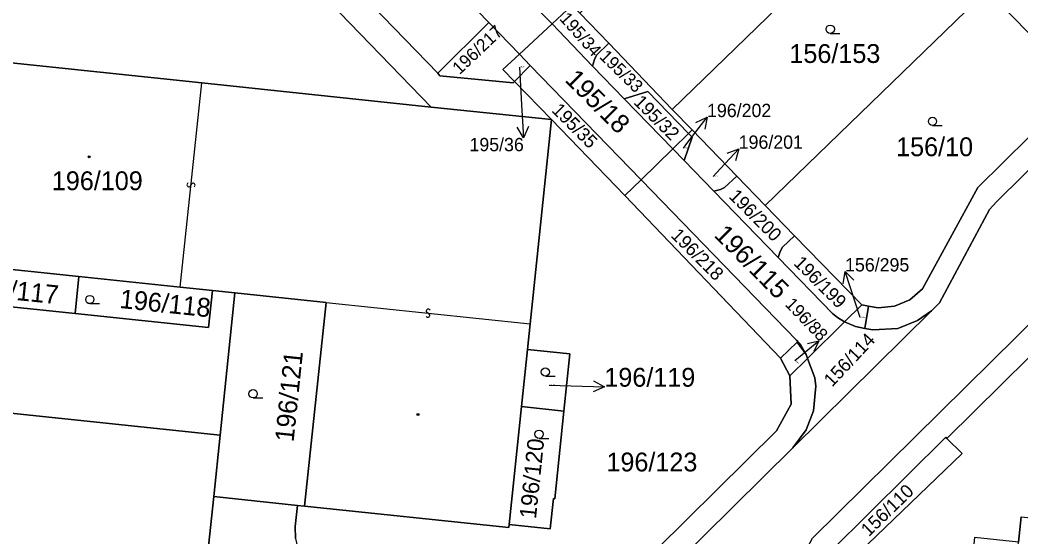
# Model space of a CAD drawing. Extents: x -598233 to -596890, y -1157848 to -1156431.
# Drawn here: x -597801.7 to -597711.3, y -1156746.8 to -1156700.1 of the extents above; entities that cross this region are included whole.
import ezdxf

# ---------------------------------------------------------------- set-up
doc = ezdxf.new("R2010")
doc.units = 0
for name, color, linetype in [('Level 1', 7, 'Continuous'), ('Level 13', 7, 'Continuous'), ('Level 3', 7, 'Continuous'), ('Level 4', 7, 'Continuous'), ('Level 5', 7, 'Continuous'), ('Level 57', 7, 'Continuous'), ('Level 60', 7, 'Continuous')]:
    doc.layers.add(name, color=color, linetype=linetype)

msp = doc.modelspace()

# ---------------------------------------------------------------- linework, layer by layer
at = {"layer": 'Level 1'}
for points in [[(-597786.04, -1156675.75), (-597787.57, -1156684.23), (-597764.57, -1156707.96)], [(-597759.36, -1156700.34), (-597781.05, -1156677.98)], [(-597785.73, -1156682.48), (-597763.99, -1156704.91)], [(-597742.79, -1156708.17), (-597722.73, -1156688.74)], [(-597686.53, -1156689.82), (-597686.5, -1156690.8), (-597687.19, -1156693.55), (-597687.81, -1156694.8), (-597689.13, -1156696.52), (-597689.98, -1156697.26), (-597690.52, -1156697.64), (-597698.5, -1156701.76), (-597699.2, -1156702.39), (-597713.49, -1156716.51), (-597714.13, -1156717.22), (-597718.64, -1156725.65), (-597719.37, -1156726.36)], [(-597750.17, -1156770.82), (-597735.18, -1156755.99), (-597734.6, -1156755.26), (-597730.11, -1156746.9), (-597683.93, -1156701.31), (-597681.14, -1156698.43), (-597679.19, -1156696.78), (-597678.75, -1156696.58)], [(-597714.33, -1156697.41), (-597734.39, -1156716.85)], [(-597714.33, -1156697.41), (-597705.92, -1156706.09)], [(-597755.85, -1156698.19), (-597753.66, -1156700.46)], [(-597753.66, -1156700.46), (-597751.84, -1156698.77)], [(-597751.16, -1156699.47), (-597748.53, -1156702.2)], [(-597763.99, -1156704.91), (-597759.36, -1156700.34)], [(-597759.36, -1156700.34), (-597756.61, -1156703.19)], [(-597756.61, -1156703.19), (-597753.66, -1156700.46)], [(-597753.66, -1156700.46), (-597749.99, -1156704.26)], [(-597749.99, -1156704.26), (-597749.83, -1156703.68), (-597749.63, -1156703.29), (-597748.53, -1156702.2)], [(-597748.53, -1156702.2), (-597742.79, -1156708.17)], [(-597757.04, -1156705.66), (-597758.1, -1156704.57), (-597756.61, -1156703.19)], [(-597756.61, -1156703.19), (-597755.62, -1156704.21)], [(-597803.73, -1156704.01), (-597803.71, -1156703.85), (-597785.3, -1156705.78)], [(-597763.99, -1156704.91), (-597763.8, -1156705.15), (-597757.17, -1156705.79), (-597757.04, -1156705.66)], [(-597755.62, -1156704.21), (-597757.04, -1156705.66)], [(-597755.62, -1156704.21), (-597745.61, -1156714.53)], [(-597747.13, -1156707.21), (-597749.99, -1156704.26)], [(-597785.3, -1156705.78), (-597764.57, -1156707.96)], [(-597753.71, -1156709.1), (-597757.04, -1156705.66)], [(-597747.13, -1156707.21), (-597745, -1156706.57), (-597741.34, -1156710.34)], [(-597725.07, -1156725.94), (-597724.19, -1156726.11), (-597722.7, -1156725.95), (-597721.32, -1156725.36), (-597720.17, -1156724.39), (-597715.17, -1156715.23), (-597705.92, -1156706.09)], [(-597742.75, -1156711.73), (-597747.13, -1156707.21)], [(-597764.57, -1156707.96), (-597753.71, -1156709.1)], [(-597741.01, -1156710.02), (-597742.79, -1156708.17)], [(-597753.71, -1156709.1), (-597755.63, -1156727.55)], [(-597753.71, -1156709.1), (-597747.07, -1156715.96)], [(-597742.75, -1156711.73), (-597741.34, -1156710.34)], [(-597741.73, -1156712.78), (-597741, -1156710.69), (-597741.34, -1156710.34)], [(-597741.34, -1156710.34), (-597741.01, -1156710.02)], [(-597741.01, -1156710.02), (-597736.95, -1156714.21)], [(-597808.32, -1156710.99), (-597809.81, -1156725.24), (-597796.75, -1156726.6)], [(-597796.4, -1156723.28), (-597805.64, -1156722.31), (-597804.5, -1156711.39)], [(-597745.61, -1156714.53), (-597742.75, -1156711.73)], [(-597741.73, -1156712.78), (-597742.75, -1156711.73)], [(-597739.05, -1156715.55), (-597741.73, -1156712.78)], [(-597745.61, -1156714.53), (-597747.07, -1156715.96)], [(-597745.61, -1156714.53), (-597731.56, -1156729.03), (-597731.19, -1156729.48), (-597730.7, -1156730.32)], [(-597739.05, -1156715.55), (-597738.44, -1156715.42), (-597738.06, -1156715.24), (-597736.95, -1156714.21)], [(-597736.95, -1156714.21), (-597734.39, -1156716.85)], [(-597733.22, -1156721.56), (-597739.05, -1156715.55)], [(-597733.02, -1156730.64), (-597747.07, -1156715.96)], [(-597734.39, -1156716.85), (-597731.74, -1156719.58)], [(-597733.22, -1156721.56), (-597733.04, -1156721.02), (-597732.82, -1156720.63), (-597731.74, -1156719.58)], [(-597731.74, -1156719.58), (-597725.66, -1156725.82)], [(-597727.22, -1156727.36), (-597727.87, -1156726.98), (-597728.31, -1156726.62), (-597733.22, -1156721.56)], [(-597796.4, -1156723.28), (-597796.75, -1156726.6)], [(-597796.4, -1156723.28), (-597787.25, -1156724.23)], [(-597796.75, -1156726.6), (-597784.7, -1156727.86), (-597784.35, -1156724.54)], [(-597787.25, -1156724.23), (-597784.35, -1156724.54)], [(-597784.35, -1156724.54), (-597782.31, -1156724.75)], [(-597782.31, -1156724.75), (-597783.65, -1156737.59)], [(-597782.31, -1156724.75), (-597774.08, -1156725.61)], [(-597776.01, -1156744.01), (-597774.08, -1156725.61)], [(-597727.22, -1156727.36), (-597725.66, -1156725.82)], [(-597725.66, -1156725.82), (-597725.07, -1156725.94)], [(-597717.97, -1156737.89), (-597705.61, -1156725.68)], [(-597731.89, -1156738.74), (-597719.37, -1156726.36)], [(-597725.07, -1156725.94), (-597725.4, -1156727.96)], [(-597719.37, -1156726.36), (-597720.64, -1156727.23), (-597722.41, -1156727.95), (-597724.67, -1156728.09), (-597725.4, -1156727.96)], [(-597755.87, -1156729.85), (-597755.63, -1156727.55)], [(-597730.57, -1156730.67), (-597727.22, -1156727.36)], [(-597725.4, -1156727.96), (-597726.23, -1156727.78), (-597727.22, -1156727.36)], [(-597730.7, -1156730.32), (-597731.52, -1156729.19), (-597733.02, -1156730.64)], [(-597756.41, -1156735.02), (-597755.87, -1156729.85)], [(-597752.58, -1156735.42), (-597752.04, -1156730.25), (-597755.87, -1156729.85)], [(-597730.7, -1156730.32), (-597730.57, -1156730.67)], [(-597733.02, -1156730.64), (-597732.17, -1156732.25)], [(-597732.17, -1156732.25), (-597730.57, -1156730.67)], [(-597731.89, -1156738.74), (-597730.68, -1156737.11), (-597730.03, -1156735.4), (-597729.82, -1156733.16), (-597729.92, -1156732.43), (-597730.57, -1156730.67)], [(-597760.41, -1156763.93), (-597733.37, -1156737.22), (-597732.06, -1156734.8), (-597732.17, -1156732.25)], [(-597813.46, -1156734.47), (-597783.65, -1156737.59)], [(-597757.52, -1156745.67), (-597756.41, -1156735.02)], [(-597752.58, -1156735.42), (-597753.41, -1156743.34), (-597753.54, -1156743.32), (-597753.82, -1156746.05), (-597757.52, -1156745.67)], [(-597752.58, -1156735.42), (-597756.41, -1156735.02)], [(-597783.65, -1156737.59), (-597784.23, -1156743.15)], [(-597717.97, -1156737.89), (-597718.07, -1156737.79), (-597728.48, -1156748.08), (-597731.29, -1156753.36)], [(-597731.29, -1156753.36), (-597716.61, -1156739.26), (-597717.97, -1156737.89)], [(-597731.89, -1156738.74), (-597756.11, -1156762.68)], [(-597784.23, -1156743.15), (-597784.97, -1156750.15)], [(-597784.23, -1156743.15), (-597776.66, -1156743.94)], [(-597776.66, -1156743.94), (-597776.86, -1156745.86), (-597776.85, -1156746.93), (-597776.61, -1156747.97), (-597776.15, -1156748.94), (-597775.48, -1156749.77), (-597762.97, -1156762.45), (-597761.74, -1156763.35), (-597760.41, -1156763.93)], [(-597776.01, -1156744.01), (-597776.66, -1156743.94)], [(-597757.52, -1156745.67), (-597757.55, -1156745.95), (-597776.01, -1156744.01)], [(-597711.51, -1156747.26), (-597711.27, -1156744.96), (-597692.75, -1156746.9)]]:
    msp.add_lwpolyline(points, dxfattribs=at)
at = {"layer": 'Level 13'}
for centre, start, end in [((-597786.463, -1156714.979), 121.33948, 353.43748), ((-597786.097, -1156715.02), 301.12502, 173.71503), ((-597764.88, -1156726.763), 211.15574, 83.74574), ((-597764.839, -1156726.397), 31.37019, 263.46819)]:
    msp.add_arc(centre, 0.184, start, end, dxfattribs=at)
at = {"layer": 'Level 3'}
for points in [[(-597787.25, -1156724.23), (-597785.3, -1156705.78)], [(-597774.08, -1156725.61), (-597755.63, -1156727.55)]]:
    msp.add_lwpolyline(points, dxfattribs=at)
at = {"layer": 'Level 5'}
for p, q in [((-597728.52, -1156701.31), (-597727.645, -1156701.31)), ((-597719.28, -1156709.63), (-597718.405, -1156709.63)), ((-597795.42, -1156725.72), (-597794.545, -1156725.72)), ((-597754.26, -1156732.27), (-597753.385, -1156732.27)), ((-597780.67, -1156734.23), (-597779.795, -1156734.23)), ((-597754.83, -1156737.89), (-597753.955, -1156737.89))]:
    msp.add_line(p, q, dxfattribs=at)
for centre, radius in [((-597728.52, -1156700.935), 0.375), ((-597719.28, -1156709.255), 0.375), ((-597795.47, -1156712.46), 0.09), ((-597795.47, -1156712.46), 0.0521), ((-597795.42, -1156725.345), 0.375), ((-597754.26, -1156731.895), 0.375), ((-597780.67, -1156733.855), 0.375), ((-597765.77, -1156735.73), 0.09), ((-597765.77, -1156735.73), 0.0521), ((-597754.83, -1156737.515), 0.375)]:
    msp.add_circle(centre, radius, dxfattribs=at)
at = {"layer": 'Level 57'}
for p, q in [((-597756.59, -1156704.37), (-597756.406, -1156707.754)), ((-597756.406, -1156707.754), (-597756.243, -1156710.75)), ((-597741.468, -1156711.257), (-597739.65, -1156708.87)), ((-597741.79, -1156711.68), (-597741.468, -1156711.257)), ((-597738.812, -1156713.946), (-597736.79, -1156711.73)), ((-597739.09, -1156714.25), (-597738.812, -1156713.946)), ((-597726.249, -1156725.663), (-597727.178, -1156722.81)), ((-597725.82, -1156726.98), (-597726.249, -1156725.663)), ((-597731.73, -1156730.85), (-597729.562, -1156729.08)), ((-597753.91, -1156733.07), (-597751.929, -1156733.13)), ((-597751.929, -1156733.13), (-597748.93, -1156733.22))]:
    msp.add_line(p, q, dxfattribs=at)
for points in [[(-597740.654, -1156709.363), (-597739.65, -1156708.87), (-597739.858, -1156709.969)], [(-597755.798, -1156709.724), (-597756.243, -1156710.75), (-597756.797, -1156709.778)], [(-597737.833, -1156712.132), (-597736.79, -1156711.73), (-597737.094, -1156712.806)], [(-597727.344, -1156723.916), (-597727.178, -1156722.81), (-597726.393, -1156723.606)], [(-597730.58, -1156729.309), (-597729.562, -1156729.08), (-597729.99, -1156730.032)], [(-597749.915, -1156732.69), (-597748.93, -1156733.22), (-597749.945, -1156733.69)]]:
    msp.add_lwpolyline(points, dxfattribs=at)
at = {"layer": 'Level 60'}
for points in [[(-597758.66, -1156695.3), (-597755.85, -1156698.19), (-597753.66, -1156700.46), (-597756.61, -1156703.19), (-597759.36, -1156700.34), (-597781.05, -1156677.98), (-597784.31, -1156674.6), (-597802.37, -1156656.01), (-597802.98, -1156655.49), (-597803.61, -1156655.05), (-597803.97, -1156654.86), (-597800.51, -1156651.51), (-597800.34, -1156651.88), (-597799.75, -1156652.82), (-597799.22, -1156653.5), (-597797.9, -1156654.85), (-597788.48, -1156664.57), (-597788.15, -1156664.91), (-597781.88, -1156671.38), (-597779.16, -1156674.17), (-597773.74, -1156679.76), (-597772.75, -1156680.78), (-597766.77, -1156686.93), (-597764.08, -1156689.7)], [(-597803.61, -1156655.05), (-597802.98, -1156655.49), (-597802.37, -1156656.01), (-597784.31, -1156674.6), (-597785.73, -1156682.48), (-597763.99, -1156704.91), (-597763.8, -1156705.15), (-597757.17, -1156705.79), (-597757.04, -1156705.66), (-597753.71, -1156709.1), (-597764.57, -1156707.96), (-597787.57, -1156684.23), (-597786.04, -1156675.75), (-597802.93, -1156658.3), (-597803.94, -1156657.35), (-597804.47, -1156656.94), (-597805.39, -1156656.47), (-597805.59, -1156656.43), (-597803.97, -1156654.86)], [(-597785.73, -1156682.48), (-597781.05, -1156677.98), (-597759.36, -1156700.34), (-597763.99, -1156704.91)], [(-597731.13, -1156680.06), (-597728.12, -1156683.17), (-597722.73, -1156688.74), (-597742.79, -1156708.17), (-597748.53, -1156702.2), (-597751.16, -1156699.47)], [(-597691.31, -1156695.88), (-597700.52, -1156700.76), (-597705.92, -1156706.09), (-597714.33, -1156697.41), (-597720.28, -1156691.27), (-597715.27, -1156686.43), (-597709.77, -1156692.11), (-597705.64, -1156688.12), (-597703.24, -1156690.6), (-597698.34, -1156685.84), (-597690.1, -1156694.34), (-597690.58, -1156694.95)], [(-597722.73, -1156688.74), (-597720.28, -1156691.27), (-597714.33, -1156697.41), (-597734.39, -1156716.85), (-597736.95, -1156714.21), (-597741.01, -1156710.02), (-597742.79, -1156708.17)], [(-597755.23, -1156698.02), (-597754.82, -1156697.85), (-597753.73, -1156696.79), (-597751.84, -1156698.77), (-597753.66, -1156700.46), (-597755.85, -1156698.19)], [(-597752.83, -1156773.83), (-597750.17, -1156770.82), (-597735.18, -1156755.99), (-597734.6, -1156755.26), (-597730.11, -1156746.9), (-597683.93, -1156701.31), (-597681.14, -1156698.43), (-597679.19, -1156696.78), (-597678.75, -1156696.58), (-597675.04, -1156699.81), (-597675.83, -1156699.36), (-597676.94, -1156699.05), (-597678.16, -1156699.1), (-597679.43, -1156699.58), (-597680.62, -1156700.99), (-597705.61, -1156725.68), (-597717.97, -1156737.89), (-597718.07, -1156737.79), (-597728.48, -1156748.08), (-597731.29, -1156753.36), (-597746.94, -1156768.39), (-597753.8, -1156775.21)], [(-597724.19, -1156726.11), (-597725.07, -1156725.94), (-597725.66, -1156725.82), (-597731.74, -1156719.58), (-597734.39, -1156716.85), (-597714.33, -1156697.41), (-597705.92, -1156706.09), (-597715.17, -1156715.23), (-597720.17, -1156724.39), (-597721.32, -1156725.36), (-597722.7, -1156725.95)], [(-597749.83, -1156703.68), (-597749.99, -1156704.26), (-597753.66, -1156700.46), (-597751.84, -1156698.77), (-597751.16, -1156699.47), (-597748.53, -1156702.2), (-597749.63, -1156703.29)], [(-597763.99, -1156704.91), (-597759.36, -1156700.34), (-597756.61, -1156703.19), (-597758.1, -1156704.57), (-597757.04, -1156705.66), (-597757.17, -1156705.79), (-597763.8, -1156705.15)], [(-597749.99, -1156704.26), (-597747.13, -1156707.21), (-597742.75, -1156711.73), (-597745.61, -1156714.53), (-597755.62, -1156704.21), (-597756.61, -1156703.19), (-597753.66, -1156700.46)], [(-597745, -1156706.57), (-597747.13, -1156707.21), (-597749.99, -1156704.26), (-597749.83, -1156703.68), (-597749.63, -1156703.29), (-597748.53, -1156702.2), (-597742.79, -1156708.17), (-597741.01, -1156710.02), (-597741.34, -1156710.34)], [(-597756.61, -1156703.19), (-597755.62, -1156704.21), (-597757.04, -1156705.66), (-597758.1, -1156704.57)], [(-597796.4, -1156723.28), (-597805.64, -1156722.31), (-597804.5, -1156711.39), (-597803.73, -1156704.01), (-597803.71, -1156703.85), (-597785.3, -1156705.78), (-597764.57, -1156707.96), (-597753.71, -1156709.1), (-597755.63, -1156727.55), (-597755.87, -1156729.85), (-597756.41, -1156735.02), (-597757.52, -1156745.67), (-597757.55, -1156745.95), (-597776.01, -1156744.01), (-597774.08, -1156725.61), (-597782.31, -1156724.75), (-597784.35, -1156724.54), (-597787.25, -1156724.23)], [(-597745.61, -1156714.53), (-597747.07, -1156715.96), (-597753.71, -1156709.1), (-597757.04, -1156705.66), (-597755.62, -1156704.21)], [(-597747.13, -1156707.21), (-597745, -1156706.57), (-597741.34, -1156710.34), (-597742.75, -1156711.73)], [(-597741, -1156710.69), (-597741.73, -1156712.78), (-597742.75, -1156711.73), (-597741.34, -1156710.34)], [(-597738.44, -1156715.42), (-597739.05, -1156715.55), (-597741.73, -1156712.78), (-597741, -1156710.69), (-597741.34, -1156710.34), (-597741.01, -1156710.02), (-597736.95, -1156714.21), (-597738.06, -1156715.24)], [(-597809.81, -1156725.24), (-597808.32, -1156710.99), (-597804.5, -1156711.39), (-597805.64, -1156722.31), (-597796.4, -1156723.28), (-597796.75, -1156726.6)], [(-597730.57, -1156730.67), (-597730.7, -1156730.32), (-597731.19, -1156729.48), (-597731.56, -1156729.03), (-597745.61, -1156714.53), (-597742.75, -1156711.73), (-597741.73, -1156712.78), (-597739.05, -1156715.55), (-597733.22, -1156721.56), (-597728.31, -1156726.62), (-597727.87, -1156726.98), (-597727.22, -1156727.36)], [(-597731.56, -1156729.03), (-597731.19, -1156729.48), (-597730.7, -1156730.32), (-597731.52, -1156729.19), (-597733.02, -1156730.64), (-597747.07, -1156715.96), (-597745.61, -1156714.53)], [(-597733.04, -1156721.02), (-597733.22, -1156721.56), (-597739.05, -1156715.55), (-597738.44, -1156715.42), (-597738.06, -1156715.24), (-597736.95, -1156714.21), (-597734.39, -1156716.85), (-597731.74, -1156719.58), (-597732.82, -1156720.63)], [(-597727.87, -1156726.98), (-597728.31, -1156726.62), (-597733.22, -1156721.56), (-597733.04, -1156721.02), (-597732.82, -1156720.63), (-597731.74, -1156719.58), (-597725.66, -1156725.82), (-597727.22, -1156727.36)], [(-597784.7, -1156727.86), (-597796.75, -1156726.6), (-597796.4, -1156723.28), (-597787.25, -1156724.23), (-597784.35, -1156724.54)], [(-597776.01, -1156744.01), (-597776.66, -1156743.94), (-597784.23, -1156743.15), (-597783.65, -1156737.59), (-597782.31, -1156724.75), (-597774.08, -1156725.61)], [(-597725.4, -1156727.96), (-597726.23, -1156727.78), (-597727.22, -1156727.36), (-597725.66, -1156725.82), (-597725.07, -1156725.94)], [(-597720.64, -1156727.23), (-597719.37, -1156726.36), (-597731.89, -1156738.74), (-597730.68, -1156737.11), (-597730.03, -1156735.4), (-597729.82, -1156733.16), (-597729.92, -1156732.43), (-597730.57, -1156730.67), (-597727.22, -1156727.36), (-597726.23, -1156727.78), (-597725.4, -1156727.96), (-597724.67, -1156728.09), (-597722.41, -1156727.95)], [(-597730.57, -1156730.67), (-597732.17, -1156732.25), (-597733.02, -1156730.64), (-597731.52, -1156729.19), (-597730.7, -1156730.32)], [(-597752.04, -1156730.25), (-597752.58, -1156735.42), (-597756.41, -1156735.02), (-597755.87, -1156729.85)], [(-597756.11, -1156762.68), (-597756.95, -1156763.31), (-597758, -1156763.78), (-597759.75, -1156763.98), (-597760.41, -1156763.93), (-597733.37, -1156737.22), (-597732.06, -1156734.8), (-597732.17, -1156732.25), (-597730.57, -1156730.67), (-597729.92, -1156732.43), (-597729.82, -1156733.16), (-597730.03, -1156735.4), (-597730.68, -1156737.11), (-597731.89, -1156738.74)], [(-597785.58, -1156755.99), (-597784.59, -1156756.09), (-597784.84, -1156758.45), (-597785.38, -1156763.63), (-597786.52, -1156774.55), (-597795.74, -1156773.59), (-597804.98, -1156772.62), (-597803.83, -1156761.7), (-597803.05, -1156754.22), (-597805.88, -1156753.92), (-597811.48, -1156753.34), (-597815.37, -1156752.93), (-597824.55, -1156751.97), (-597833.78, -1156751.01), (-597832.65, -1156740.21), (-597832.09, -1156734.89), (-597831.85, -1156732.55), (-597813.46, -1156734.47), (-597783.65, -1156737.59), (-597784.23, -1156743.15), (-597784.97, -1156750.15)], [(-597752.58, -1156735.42), (-597753.41, -1156743.34), (-597753.54, -1156743.32), (-597753.82, -1156746.05), (-597757.52, -1156745.67), (-597756.41, -1156735.02)], [(-597718.07, -1156737.79), (-597717.97, -1156737.89), (-597716.61, -1156739.26), (-597731.29, -1156753.36), (-597728.48, -1156748.08)], [(-597776.66, -1156743.94), (-597776.86, -1156745.86), (-597776.85, -1156746.93), (-597776.61, -1156747.97), (-597776.15, -1156748.94), (-597775.48, -1156749.77), (-597762.97, -1156762.45), (-597761.74, -1156763.35), (-597760.41, -1156763.93), (-597765.61, -1156769.06), (-597766.01, -1156767.86), (-597766.84, -1156766.68), (-597782.48, -1156750.95), (-597783.13, -1156750.48), (-597783.9, -1156750.26), (-597784.97, -1156750.15), (-597784.23, -1156743.15)], [(-597665.43, -1156753.24), (-597661.81, -1156755.91), (-597663.15, -1156768.63), (-597663.38, -1156770.88), (-597663.95, -1156776.26), (-597665.06, -1156786.8), (-597665.09, -1156787.1), (-597683.58, -1156785.16), (-597681.65, -1156766.76), (-597689.84, -1156765.9), (-597691.75, -1156765.7), (-597694.73, -1156765.39), (-597703.96, -1156764.43), (-597713.21, -1156763.46), (-597712.08, -1156752.7), (-597711.51, -1156747.26), (-597711.27, -1156744.96), (-597692.75, -1156746.9), (-597670.98, -1156749.18)]]:
    msp.add_lwpolyline(points, close=True, dxfattribs=at)
for points in [[(-597787.57, -1156684.23), (-597764.57, -1156707.96), (-597785.3, -1156705.78), (-597803.71, -1156703.85)], [(-597683.93, -1156701.31), (-597730.11, -1156746.9)], [(-597756.11, -1156762.68), (-597731.89, -1156738.74), (-597719.37, -1156726.36), (-597718.64, -1156725.65), (-597714.13, -1156717.22), (-597713.49, -1156716.51), (-597699.2, -1156702.39)], [(-597699.2, -1156702.39), (-597713.49, -1156716.51), (-597714.13, -1156717.22), (-597718.64, -1156725.65), (-597719.37, -1156726.36), (-597720.64, -1156727.23), (-597722.41, -1156727.95), (-597724.67, -1156728.09), (-597725.4, -1156727.96), (-597725.07, -1156725.94), (-597724.19, -1156726.11), (-597722.7, -1156725.95), (-597721.32, -1156725.36), (-597720.17, -1156724.39), (-597715.17, -1156715.23), (-597705.92, -1156706.09)], [(-597776.85, -1156746.93), (-597776.86, -1156745.86), (-597776.66, -1156743.94), (-597776.01, -1156744.01), (-597757.55, -1156745.95), (-597757.52, -1156745.67), (-597753.82, -1156746.05), (-597753.54, -1156743.32), (-597753.41, -1156743.34), (-597752.58, -1156735.42), (-597752.04, -1156730.25), (-597755.87, -1156729.85), (-597755.63, -1156727.55), (-597753.71, -1156709.1), (-597747.07, -1156715.96), (-597733.02, -1156730.64), (-597732.17, -1156732.25), (-597732.06, -1156734.8), (-597733.37, -1156737.22), (-597760.41, -1156763.93)], [(-597809.81, -1156725.24), (-597796.75, -1156726.6), (-597784.7, -1156727.86), (-597784.35, -1156724.54), (-597782.31, -1156724.75), (-597783.65, -1156737.59), (-597813.46, -1156734.47)], [(-597691.18, -1156778.7), (-597720.91, -1156775.59), (-597739.41, -1156773.66), (-597739.65, -1156775.95), (-597743.58, -1156775.54), (-597744.14, -1156780.92), (-597745.4, -1156792.91), (-597764.59, -1156790.9), (-597757.86, -1156784.17), (-597751.4, -1156775.05), (-597733.27, -1156757.08), (-597731.29, -1156753.36), (-597716.61, -1156739.26), (-597717.97, -1156737.89), (-597705.61, -1156725.68)], [(-597711.27, -1156744.96), (-597711.51, -1156747.26), (-597715.49, -1156746.85), (-597716.06, -1156752.28), (-597717.61, -1156767.02), (-597704.38, -1156768.41)]]:
    msp.add_lwpolyline(points, dxfattribs=at)

# ---------------------------------------------------------------- texts
at = {"layer": 'Level 4'}
for s, height, rotation, p in [('195/34', 1.14, 311.57163, (-597753.05, -1156700.02)), ('196/217', 1.14, 43.44426, (-597762.01, -1156705.09)), ('195/33', 1.14, 315.60309, (-597749.45, -1156703.49)), ('195/18', 1.7, 315, (-597752.58, -1156705.58)), ('195/35', 1.2, 315, (-597753.754, -1156708.326)), ('195/32', 1.2, 315, (-597746.356, -1156707.594)), ('196/200', 1.2, 315, (-597737.754, -1156716.096)), ('196/218', 1.2, 315, (-597742.986, -1156719.634)), ('196/115', 1.7, 315, (-597739.11, -1156719.61)), ('196/199', 1.2, 315, (-597731.895, -1156722.135)), ('196/117', 1.7, 354.05496, (-597806.511, -1156724.929)), ('196/118', 1.7, 354.03057, (-597792.774, -1156726.102)), ('156/114', 1.2, 46.8, (-597728.348, -1156733.304)), ('196/121', 1.7, 84.01203, (-597777.014, -1156738.261)), ('196/88', 0.1, 313.87671, (-597731.73, -1156730.85)), ('196/120', 1.5, 84.01734, (-597755.111, -1156745.196)), ('156/110', 1.2, 44.1, (-597725.04, -1156746.817))]:
    msp.add_text(s, height=height, rotation=rotation, dxfattribs=at).set_placement(p)
for s, height, p in [('156/153', 1.7, (-597732.211, -1156703.98)), ('195/36', 0.1, (-597756.59, -1156704.37)), ('156/10', 1.7, (-597722.568, -1156712.4)), ('196/202', 0.1, (-597741.79, -1156711.68)), ('196/109', 1.7, (-597798.855, -1156715.47)), ('196/201', 0.1, (-597739.09, -1156714.25)), ('156/295', 0.1, (-597725.82, -1156726.98)), ('196/119', 0.1, (-597753.91, -1156733.07)), ('196/123', 1.7, (-597748.743, -1156740.87))]:
    msp.add_text(s, height=height, dxfattribs=at).set_placement(p)
at = {"layer": 'Level 57'}
for s, height, p in [('196/202', 1.2, (-597739.65, -1156708.87)), ('196/201', 1.2, (-597736.79, -1156711.73)), ('195/36', 1.2, (-597761.117, -1156711.95)), ('156/295', 1.2, (-597727.178, -1156722.81)), ('196/119', 1.7, (-597748.93, -1156733.22))]:
    msp.add_text(s, height=height, dxfattribs=at).set_placement(p)
msp.add_text('196/88', height=1.14, rotation=313.87671, dxfattribs=at).set_placement((-597732.678, -1156725.84))

doc.saveas('drawing.dxf')
